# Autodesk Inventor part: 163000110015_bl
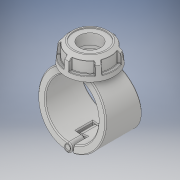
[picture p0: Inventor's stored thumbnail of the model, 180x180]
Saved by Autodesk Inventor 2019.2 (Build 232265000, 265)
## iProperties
Created: 2022-02
Part Number: 163000110015_bl
Material: Generic
Description: Plassadle Threaded 110x1 1/2''
Document SubType Name: Modeling
Designer: comp2
Density: 1 g/cm^3
Appearance: Default
Author: comp2
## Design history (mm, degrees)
derived "16300.ipt"
feature "Solid1::16300.ipt" dims "ScaleForDerivedMember" = 10
feature "Solid2::16300.ipt" dims "ScaleForDerivedMember" = 10
feature "Solid3::16300.ipt" dims "ScaleForDerivedMember" = 10
feature "Solid4::16300.ipt" dims "ScaleForDerivedMember" = 10
tag "TaggingFeature1"
body "Solid1"
body "Solid2"
body "Solid3"
body "Solid4"
other parameters: "d2" = 141 [user parameter], "d3" = 55 [user parameter], "d7" = 133.95 [user parameter], "d8" = 85 deg [user parameter], "d9" = 45 deg [user parameter], "d10" = 102 [user parameter], "d11" = 49 [user parameter], "d12" = 27.7935 [user parameter], "d13" = 42.84 [user parameter], "d14" = 67.2675 [user parameter], "d42" = 3.1 [user parameter], "d49" = 2.82 [user parameter], "d50" = 97 [user parameter], "d51" = 0 [user parameter], "d52" = 21.7 [user parameter], "d53" = 77.55 [user parameter], "d54" = 33.95 [user parameter], "d55" = 0 [user parameter], "d56" = 19.4 [user parameter], "d57" = 19.4 [user parameter], "d59" = 0 [user parameter], "d60" = 97 [user parameter], "d61" = 0 [user parameter], "d62" = 33.95 [user parameter], "d63" = 0 [user parameter], "d65" = 0 [user parameter], "d67" = 0 [user parameter], "d69" = 0 [user parameter], "d70" = 1 [user parameter], "d71" = 93.12 [user parameter], "d72" = 0 [user parameter], "d73" = 2 [user parameter], "d78" = 86.7 [user parameter], "d79" = 5.1 [user parameter], "d80" = 60 deg [user parameter], "d81" = 5.1 [user parameter], "d84" = 0 [user parameter], "d85" = 1 [user parameter], "d87" = 360 deg [user parameter], "d122" = 49 [user parameter], "d124" = 42.80128 [user parameter], "d125" = 1.98525 [user parameter], "d129" = 44.845 [user parameter], "d130" = 38.11825 [user parameter], "d131" = 31.85 [user parameter], "d132" = 45 deg [user parameter], "d133" = 22.295 [user parameter], "d134" = 22.4225 [user parameter], "d136" = 0 [user parameter], "d138" = 0 [user parameter], "d1" = 25 [user parameter], "B" = 141 [user parameter], "L" = 97 [user parameter], "E_" = 54 [user parameter], "E1" = 102 [user parameter], "H2" = 49 [user parameter], "H3" = 78 [user parameter], "H_costum" = 49 [user parameter], "Rp" = 44.845 [user parameter], "d128" = 39.705 [user parameter]
